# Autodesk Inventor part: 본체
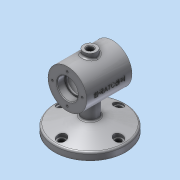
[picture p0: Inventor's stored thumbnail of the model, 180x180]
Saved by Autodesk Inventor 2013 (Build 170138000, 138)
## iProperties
Created: 2018-12
Part Number: 본체
Material: 알루미늄 6061
Document SubType Name: Modeling
Designer: Administrator
Density: 1 g/cm^3
Author: Administrator
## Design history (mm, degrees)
sketch "스케치1"
  geometry: C1 r 30 at (0, 0); 1 further point
  constraints: 1 centre point, 1 coincident
  dimensions: "d0" = 60 diameter of C1
extrude "돌출1" new body sketch "스케치1" distance "d1" = 35; taper "d2" = 0 deg
sketch "스케치2"
  geometry: C1 r 30 at (0, 0) reference; C2 r 16 at (0, 0)
  constraints: 1 centre point, 1 coincident
  dimensions: "d4" = 32 diameter of C2
extrude "돌출2" cut sketch "스케치2" distance "d5" = 12; taper "d6" = 0 deg
sketch "스케치3"
  geometry: C1 r 16 at (0, 0) reference; C2 r 14 at (0, 0)
  constraints: 1 centre point, 1 coincident
  dimensions: "d7" = 28 diameter of C2
extrude "돌출3" cut sketch "스케치3" distance "d8" = 3; taper "d9" = 0 deg
sketch "스케치4"
  geometry: C1 r 14 at (0, 0) reference; C2 r 25 at (0, 0)
  constraints: 1 centre point, 1 coincident
  dimensions: "d10" = 50 diameter of C2
extrude "돌출4" cut sketch "스케치4" stored distance "d11" = 3; taper "d12" = 0 deg
fillet "모깎기1" dims "d13" = 3
chamfer "모따기1" distance "d14" = 1; stored, may be unused: second distance "d15" = 2, angle "d16" = 45 deg
fillet "모깎기2" dims "d17" = 0.3
sketch "스케치5" dims "d18" = 46
  geometry: C1 r 30 at (0, 0) reference; C2 r 17 at (0, 0) reference; 2 further points
  constraints: 2 vertical alignment, 1 coincident, 2 other
hole "구멍1" sketch "스케치5" at (0, 23) diameter "d19" = 3.242; stored, may be unused: countersink angle "d23" = 90 deg, drill point angle "d25" = 118 deg; dims "d20" = 8, "d21" = 4, "d22" = 2, "d24" = 10
node "작업 평면1"
sketch "스케치6"
  geometry: C1 r 55 at (0, 0); 1 further point
  constraints: 1 centre point, 1 coincident
  dimensions: "d30" = 110 diameter of C1
extrude "돌출5" join sketch "스케치6" distance "d31" = 11; taper "d32" = 0 deg
sketch "스케치9"
  geometry: C1 r 55 at (0, 0) reference; C2 r 12 at (0, 0)
  constraints: 1 centre point, 1 coincident
  dimensions: "d36" = 24 diameter of C2
extrude "돌출7" join sketch "스케치9" stored distance "d37" = 11; taper "d38" = 0 deg
sketch "스케치10"
  geometry: C1 r 55 at (0, 0) reference; C2 r 55 at (0, 0)
  constraints: 1 centre point, 1 coincident
  dimensions: "d39" = 110 diameter of C2
extrude "돌출8" join sketch "스케치10" distance "d40" = 11; taper "d41" = -75 deg
fillet "모깎기3" dims "d42" = 3
node "작업 평면2"
sketch "스케치11"
  geometry: C1 r 10 at (0, 0); 1 further point
  constraints: 1 centre point, 1 coincident
  dimensions: "d44" = 20 diameter of C1
extrude "돌출9" join sketch "스케치11" stored distance "d45" = 11; taper "d46" = 0 deg
sketch "스케치12"
  geometry: C1 r 10 at (0, 0) reference; C2 r 5 at (0, 0)
  constraints: 1 centre point, 1 coincident
  dimensions: "d47" = 10 diameter of C2
extrude "돌출10" cut sketch "스케치12" stored distance "d48" = 11; taper "d49" = 0 deg
chamfer "모따기2" distance "d50" = 1; stored, may be unused: second distance "d51" = 2, angle "d52" = 45 deg
node "작업 평면3"
sketch "스케치13" dims "d54" = 88
  geometry: C1 r 7 at (0, 44); 2 further points
  constraints: 2 vertical alignment, 1 centre point, 1 coincident, 2 other
  dimensions: "d55" = 14 diameter of C1
extrude "돌출11" cut sketch "스케치13" distance "d56" = 11; taper "d57" = 0 deg
sketch "스케치14"
  geometry: C1 r 7 at (0, 0) reference; C2 r 4.5 at (0, 0); 1 further point
  constraints: 1 centre point, 1 coincident
  dimensions: "d58" = 9 diameter of C2
extrude "돌출12" cut sketch "스케치14" stored distance "d59" = 11; taper "d60" = 0 deg
fillet "모깎기4" dims "d64" = 3
fillet "모깎기5" dims "d65" = 3
fillet "모깎기6" dims "d66" = 3
node "작업 평면4"
sketch "스케치15"
  geometry: L1 (30, 35)-(-30, 35) reference; 2 further points
  constraints: 1 other
  dimensions: "d68" = 35 distance from line of point (0, 0) L1; "d69" = 30 horizontal distance of point (0, 0) L1.start
feature "엠보싱1" sketch "스케치15" dims "d70" = 0.5, "d71" = 0
node "솔리드1" dims "d55" = 14
pattern_circular "원형 패턴1" dims angle "d27" = 360 deg
mirror "대칭1"
pattern_circular "원형 패턴2" dims angle "d62" = 360 deg
other parameters: "d29" = -75, "d43" = -112, "d67" = 147
